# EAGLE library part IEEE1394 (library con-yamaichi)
YAMAICHI CONNECTOR Fire wire
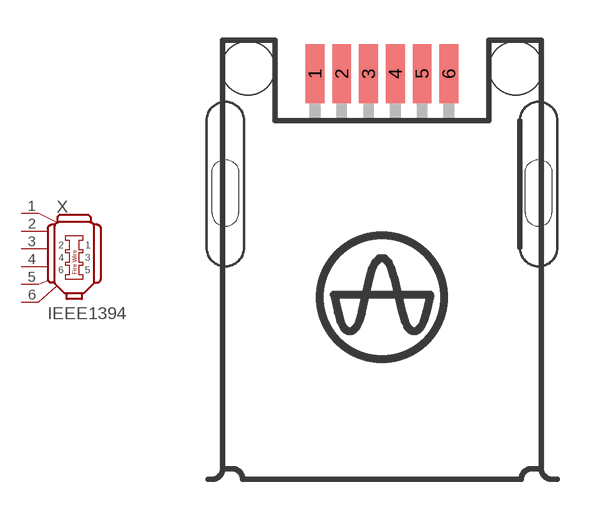
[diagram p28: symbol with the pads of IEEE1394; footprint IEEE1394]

Designator prefix X

## IEEE1394 (OC_FARNELL: unknown; OC_NEWARK: unknown)  [IEEE1394]
1  1  pas
2  2  pas
3  3  pas
4  4  pas
5  5  pas
6  6  pas

## Footprint IEEE1394 (pad centres in mm)
Fire Wire YAMAICHI CONNECTOR
smd 0.7 x 2.2: 1 -2.5,8.25; 2 -1.5,8.25; 3 -0.5,8.25; 4 0.5,8.25; 5 1.5,8.25; 6 2.5,8.25
hole 2 at -5,8.45
hole 2 at 5,8.45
